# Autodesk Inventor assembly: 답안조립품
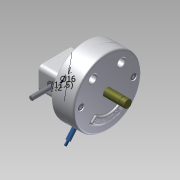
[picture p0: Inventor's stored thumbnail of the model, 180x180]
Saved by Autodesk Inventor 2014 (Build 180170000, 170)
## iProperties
Created: 2015-04
Part Number: 답안조립품
Document SubType Name: Assembly
Designer: Administrator
Mass: 3964.99 g
Surface Area: 3333.63 cm^2
Volume: 1140.85 cm^3
Density: 3.47546 g/cm^3
Author: Administrator
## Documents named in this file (15)
- C:\Documents and Settings\Administrator\바탕 화면\350406V1032\답안조립품.iam
- C:\Documents and Settings\Administrator\바탕 화면\350406V1032\본체.ipt
- C:\Documents and Settings\Administrator\바탕 화면\350406V1032\가변스프링.ipt
- C:\Documents and Settings\Administrator\바탕 화면\350406V1032\베어링62_22.ipt
- C:\Documents and Settings\Administrator\바탕 화면\350406V1032\멈춤링.ipt
- C:\Documents and Settings\Administrator\바탕 화면\350406V1032\커버.ipt
- C:\Documents and Settings\Administrator\바탕 화면\350406V1032\축.ipt
- C:\Documents and Settings\Administrator\바탕 화면\350406V1032\커버2.ipt
- C:\Documents and Settings\Administrator\바탕 화면\350406V1032\M 5 x 12.ipt
- C:\Documents and Settings\Administrator\바탕 화면\350406V1032\M 10 x 35.ipt
- C:\Documents and Settings\Administrator\바탕 화면\350406V1032\슬라이더3.ipt
- C:\Documents and Settings\Administrator\바탕 화면\350406V1032\부시.ipt
- C:\Documents and Settings\Administrator\바탕 화면\350406V1032\슬라이더.ipt
- C:\Documents and Settings\Administrator\바탕 화면\350406V1032\슬라이더2.ipt
- C:\Documents and Settings\Administrator\바탕 화면\350406V1032\평행핀.ipt
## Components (6 placed, 4 different names)
1. 가변스프링:1
2. M 5 x 12:1
3. M 5 x 12:2
4. M 10 x 35:1
5. M 10 x 35:2
6. KS B 1320 B B 5 x  20:1 — 플러쉬:1
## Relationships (1: Flush 1)
- 플러쉬:1 [Flush]: KS B 1320 B B 5 x  20:1
